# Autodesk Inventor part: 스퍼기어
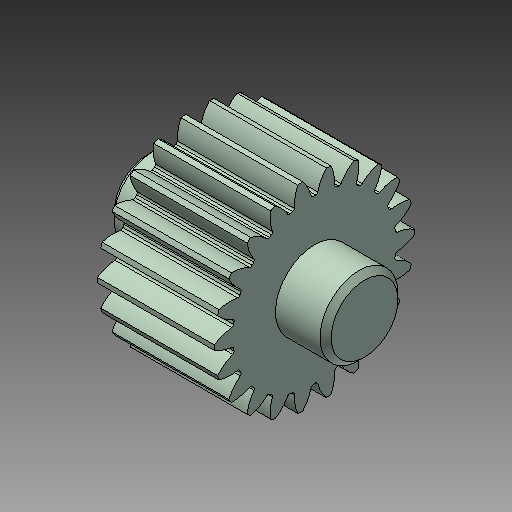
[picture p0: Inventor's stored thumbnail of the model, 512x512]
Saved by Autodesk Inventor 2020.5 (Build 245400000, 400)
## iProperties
Created: 2024-02
Part Number: 스퍼기어
Material: 강철, 탄소
Document SubType Name: Modeling
Designer: mdu-01
Density: 1 g/cm^3
Appearance: 기본값(1)
Author: mdu-01
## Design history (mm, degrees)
sketch "스케치1"
  geometry: L1 (-19.5, 0)-(19.5, 0); L2 (19.5, 0)-(19.5, 6); L3 (18.5, 7)-(10.5, 7); L4 (10.5, 7)-(10.5, 14.625); L5 (10.5, 14.625)-(-10.5, 14.625); L6 (-10.5, 14.625)-(-10.5, 7); L7 (-10.5, 7)-(-18.5, 7); L8 (-19.5, 6)-(-19.5, 0); L9 (-18.5, 7)-(-19.5, 6); L10 (19.5, 6)-(18.5, 7); L11 (-10.5, 16.5)-(10.5, 16.5); 4 further points
  constraints: 22 end point, 6 parallel, 6 point on line, 2 collinear, 2 perpendicular, 1 coincident, 1 horizontal, 1 midpoint
  dimensions: "d0" = 1 distance of L7.end point (-19.5, 7); "d1" = 1 distance of L8.start point (-19.5, 7) (= d0); "d2" = 1 distance of L2.end point (19.5, 7) (= d0); "d3" = 1 distance of L3.start point (19.5, 7) (= d2); "d4" = 9 distance between parallel lines of L8 L6; "d5" = 21 distance between parallel lines of L4 L6; "d6" = 33 diameter of L11 L1; "d7" = 1.875 distance between parallel lines of L5 L11; "d8" = 14 diameter of L7 L1
revolve "회전1" sketch "스케치1" stored, may be unused: angle "d9" = 90 deg
sketch "스케치2" dims "d10" = 33
  geometry: L1 (0, 0)-(18, 0); A1 r 18 centre (0, 0) between (17.995, -0.428) and (17.995, 0.428); A2 r 7.045 centre (14.16, 5.482) between (14.542, -1.553) and (17.995, -0.428); A3 r 7.045 centre (14.16, -5.482) between (17.995, 0.428) and (14.542, 1.553); A4 r 14.625 centre (0, 0) between (14.542, -1.553) and (14.542, 1.553); 4 further points
  constraints: 10 point on circle, 4 centre point, 3 symmetric about line, 2 coincident, 2 end point, 1 horizontal, 8 other
  dimensions: "d11" = 1.5 dimension on A1; "d12" = 1.1775 distance from line of point (16.458, -1.178) L1; "d13" = 0.75 vertical distance of A1.start point (16.458, -1.178); "d14" = 0.375 vertical distance of A2.start point (16.458, -1.178)
extrude "돌출1" join sketch "스케치2" stored distance "d15" = 10; taper "d16" = 0 deg
fillet "모깎기1" dims "d17" = 0.375
node "솔리드1"
pattern_circular "원형 패턴1" dims angle "d19" = 360 deg
